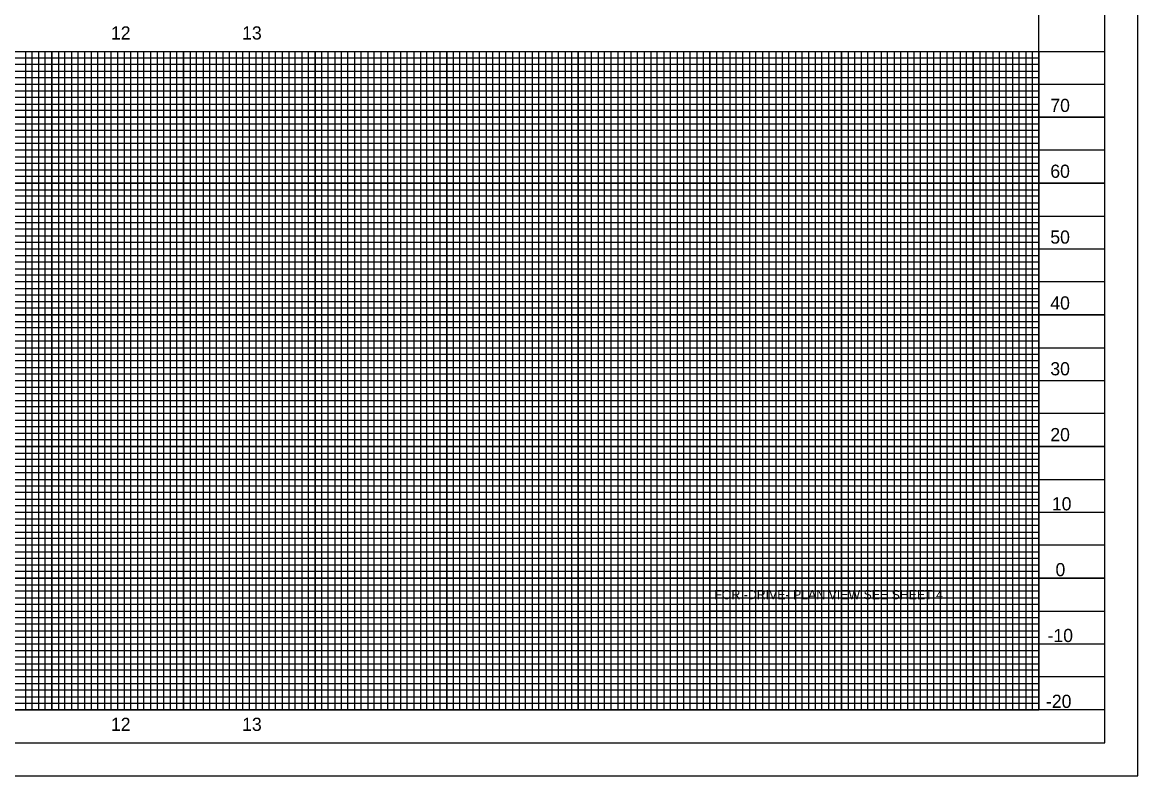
# Model space of a CAD drawing. Extents: x 1637092 to 1638792, y 884647 to 885778.
# Drawn here: x 1637944 to 1638792, y 884647 to 885219 of the extents above; entities that cross this region are included whole.
import ezdxf

# ---------------------------------------------------------------- set-up
doc = ezdxf.new("R2010")
doc.units = 0
for name, color, linetype in [('Exist Vertical Profile Horizontal Axis Label Major', 7, 'Continuous'), ('Exist Vertical Profile Vertical Axis Label', 7, 'Continuous'), ('Prop VPI Label', 7, 'Continuous'), ('Scratch_Level_3', 7, 'Continuous'), ('Sheet Cutting Line CELL', 7, 'Continuous'), ('Sheet DOT Grid CELL', 7, 'Continuous'), ('Sheet Layout Profile Border Port 2', 7, 'Continuous'), ('Sheet Plan And Profile CELL', 7, 'Continuous'), ('Sheet Profile CELL', 7, 'Continuous'), ('Sheet Profile Grid Major CELL', 7, 'Continuous'), ('Sheet Profile Grid Middle CELL', 7, 'Continuous'), ('Sheet Profile Grid Minor CELL', 7, 'Continuous'), ('Stewart Plot Border Xerox6279 and LJ5000', 7, 'Continuous')]:
    doc.layers.add(name, color=color, linetype=linetype)

msp = doc.modelspace()

# ---------------------------------------------------------------- linework, layer by layer
at = {"layer": 'Prop VPI Label'}
msp.add_lwpolyline([(1638466.66, 884797.14), (1638681.66, 884797.14), (1638681.66, 884772.14), (1638466.66, 884772.14)], close=True, dxfattribs=at)
msp.add_lwpolyline([(1638466.66, 884797.14), (1638681.66, 884797.14), (1638681.66, 884772.14), (1638466.66, 884772.14)], close=True, dxfattribs=at)
at = {"layer": 'Scratch_Level_3'}
msp.add_lwpolyline([(1637316.66, 885722.14), (1637316.66, 884697.14), (1638716.66, 884697.14), (1638716.66, 885777.71)], close=True, dxfattribs=at)
at = {"layer": 'Sheet Cutting Line CELL'}
msp.add_line((1637099.66, 884647.14), (1638783.66, 884647.14), dxfattribs=at)
at = {"layer": 'Sheet DOT Grid CELL'}
for p, q in [((1637266.66, 885197.14), (1638766.54, 885197.14)), ((1637966.66, 885197.14), (1637966.66, 884697.14)), ((1638016.66, 885197.14), (1638016.66, 884697.14)), ((1638066.66, 885197.14), (1638066.66, 884697.14)), ((1638116.66, 885197.14), (1638116.66, 884697.14)), ((1638166.66, 885197.14), (1638166.66, 884697.14)), ((1638216.66, 885197.14), (1638216.66, 884697.14)), ((1638266.66, 885197.14), (1638266.66, 884697.14)), ((1638316.66, 885197.14), (1638316.66, 884697.14)), ((1638366.66, 885197.14), (1638366.66, 884697.14)), ((1638416.66, 885197.14), (1638416.66, 884697.14)), ((1638466.66, 885197.14), (1638466.66, 884697.14)), ((1638516.66, 885197.14), (1638516.66, 884697.14)), ((1638566.66, 885197.14), (1638566.66, 884697.14)), ((1638616.66, 885197.14), (1638616.66, 884697.14)), ((1638666.66, 885197.14), (1638666.66, 884697.14)), ((1638716.66, 885197.14), (1638716.66, 884697.14)), ((1637266.66, 885147.14), (1638766.54, 885147.14)), ((1637266.66, 885097.14), (1638766.54, 885097.14)), ((1637266.66, 885047.14), (1638766.54, 885047.14)), ((1637266.66, 884997.14), (1638766.54, 884997.14)), ((1637266.66, 884947.14), (1638766.54, 884947.14)), ((1637266.66, 884897.14), (1638766.54, 884897.14)), ((1637266.66, 884847.14), (1638766.54, 884847.14)), ((1637266.66, 884797.14), (1638766.54, 884797.14)), ((1637266.66, 884747.14), (1638766.54, 884747.14))]:
    msp.add_line(p, q, dxfattribs=at)
at = {"layer": 'Sheet Layout Profile Border Port 2'}
msp.add_lwpolyline([(1637316.66, 885197.14), (1638716.66, 885197.14), (1638716.66, 884697.14), (1637316.66, 884697.14)], close=True, dxfattribs=at)
at = {"layer": 'Sheet Plan And Profile CELL'}
msp.add_lwpolyline([(1638766.66, 885722.14), (1637266.66, 885722.14), (1637266.66, 884672.14), (1638766.66, 884672.14)], close=True, dxfattribs=at)
at = {"layer": 'Sheet Profile CELL'}
for p, q in [((1637266.66, 885197.14), (1638766.66, 885197.14)), ((1638766.66, 884697.14), (1637266.66, 884697.14)), ((1638766.66, 884697.14), (1637266.66, 884697.14)), ((1637266.66, 884672.14), (1638766.66, 884672.14))]:
    msp.add_line(p, q, dxfattribs=at)
msp.add_lwpolyline([(1638766.66, 885722.14), (1637266.66, 885722.14), (1637266.66, 884672.14), (1638766.66, 884672.14)], close=True, dxfattribs=at)
at = {"layer": 'Sheet Profile Grid Major CELL'}
for p, q in [((1638266.66, 885197.14), (1638316.66, 885197.14)), ((1638366.66, 885197.14), (1638416.66, 885197.14)), ((1638466.66, 885197.14), (1638516.66, 885197.14)), ((1638566.66, 885197.14), (1638616.66, 885197.14)), ((1638666.66, 885197.14), (1638716.66, 885197.14)), ((1638666.66, 884697.14), (1638666.66, 884697.14))]:
    msp.add_line(p, q, dxfattribs=at)
for points in [[(1637916.66, 884697.14), (1637966.66, 884697.14), (1637966.66, 885197.14), (1638016.66, 885197.14), (1638016.66, 884697.14), (1638066.66, 884697.14), (1638066.66, 885197.14), (1638116.66, 885197.14), (1638116.66, 884697.14), (1638166.66, 884697.14), (1638166.66, 885197.14), (1638216.66, 885197.14), (1638216.66, 884697.14), (1638266.66, 884697.14), (1638266.66, 885197.14), (1638316.66, 885197.14), (1638316.66, 884697.14), (1638366.66, 884697.14), (1638366.66, 885197.14), (1638416.66, 885197.14), (1638416.66, 884697.14), (1638466.66, 884697.14), (1638466.66, 885197.14), (1638516.66, 885197.14), (1638516.66, 884697.14), (1638566.66, 884697.14), (1638566.66, 885197.14), (1638616.66, 885197.14), (1638616.66, 884697.14), (1638666.66, 884697.14), (1638666.66, 884697.14), (1638666.66, 885197.14), (1638716.66, 885197.14), (1638716.66, 884697.14)], [(1638766.66, 885147.14), (1637266.66, 885147.14)], [(1638766.66, 885097.14), (1637266.66, 885097.14), (1637266.66, 885047.14), (1638766.66, 885047.14)], [(1638766.66, 884997.14), (1637266.66, 884997.14), (1637266.66, 884947.14), (1638766.66, 884947.14)], [(1638766.66, 884897.14), (1637266.66, 884897.14), (1637266.66, 884847.14), (1638766.66, 884847.14)], [(1638766.66, 884797.14), (1637266.66, 884797.14), (1637266.66, 884797.14), (1637266.66, 884747.14), (1638766.66, 884747.14)], [(1638766.66, 884697.14), (1637266.66, 884697.14)]]:
    msp.add_lwpolyline(points, dxfattribs=at)
at = {"layer": 'Sheet Profile Grid Middle CELL'}
for points in [[(1637941.66, 884697.14), (1637991.66, 884697.14), (1637991.66, 885197.14), (1638041.66, 885197.14), (1638041.66, 884697.14), (1638091.66, 884697.14), (1638091.66, 885197.14), (1638141.66, 885197.14), (1638141.66, 884697.14), (1638191.66, 884697.14), (1638191.66, 885197.14), (1638241.66, 885197.14), (1638241.66, 884697.14), (1638291.66, 884697.14), (1638291.66, 885197.14), (1638341.66, 885197.14), (1638341.66, 884697.14), (1638391.66, 884697.14), (1638391.66, 885197.14), (1638441.66, 885197.14), (1638441.66, 884697.14), (1638491.66, 884697.14), (1638491.66, 885197.14), (1638541.66, 885197.14), (1638541.66, 884697.14), (1638591.66, 884697.14), (1638591.66, 885197.14), (1638641.66, 885197.14), (1638641.66, 884697.14), (1638691.66, 884697.14), (1638691.66, 885197.14)], [(1637266.66, 885172.14), (1638766.66, 885172.14)], [(1638766.66, 885122.14), (1637266.66, 885122.14), (1637266.66, 885072.14), (1638766.66, 885072.14)], [(1638766.66, 885022.14), (1637266.66, 885022.14), (1637266.66, 884972.14), (1638766.66, 884972.14)], [(1638766.66, 884922.14), (1637266.66, 884922.14), (1637266.66, 884872.14), (1638766.66, 884872.14)], [(1638766.66, 884822.14), (1637266.66, 884822.14), (1637266.66, 884772.14), (1638766.66, 884772.14)], [(1638766.66, 884722.14), (1637266.66, 884722.14)]]:
    msp.add_lwpolyline(points, dxfattribs=at)
at = {"layer": 'Sheet Profile Grid Minor CELL'}
for p, q in [((1637316.66, 885192.14), (1638716.66, 885192.14)), ((1638716.66, 885187.14), (1637316.66, 885187.14)), ((1637316.66, 885182.14), (1638716.66, 885182.14)), ((1638716.66, 885177.14), (1637316.66, 885177.14)), ((1637316.66, 885167.14), (1638716.66, 885167.14)), ((1638716.66, 885162.14), (1637316.66, 885162.14)), ((1637316.66, 885157.14), (1638716.66, 885157.14)), ((1638716.66, 885152.14), (1637316.66, 885152.14)), ((1637316.66, 885142.14), (1638716.66, 885142.14)), ((1638716.66, 885137.14), (1637316.66, 885137.14)), ((1637316.66, 885132.14), (1638716.66, 885132.14)), ((1638716.66, 885127.14), (1637316.66, 885127.14)), ((1637316.66, 885117.14), (1638716.66, 885117.14)), ((1638716.66, 885112.14), (1637316.66, 885112.14)), ((1637316.66, 885107.14), (1638716.66, 885107.14)), ((1638716.66, 885102.14), (1637316.66, 885102.14)), ((1637316.66, 885092.14), (1638716.66, 885092.14)), ((1638716.66, 885087.14), (1637316.66, 885087.14)), ((1637316.66, 885082.14), (1638716.66, 885082.14)), ((1638716.66, 885077.14), (1637316.66, 885077.14)), ((1637316.66, 885067.14), (1638716.66, 885067.14)), ((1638716.66, 885062.14), (1637316.66, 885062.14)), ((1637316.66, 885057.14), (1638716.66, 885057.14)), ((1638716.66, 885052.14), (1637316.66, 885052.14)), ((1637316.66, 885042.14), (1638716.66, 885042.14)), ((1638716.66, 885037.14), (1637316.66, 885037.14)), ((1637316.66, 885032.14), (1638716.66, 885032.14)), ((1638716.66, 885027.14), (1637316.66, 885027.14)), ((1637316.66, 885017.14), (1638716.66, 885017.14)), ((1638716.66, 885012.14), (1637316.66, 885012.14)), ((1637316.66, 885007.14), (1638716.66, 885007.14)), ((1638716.66, 885002.14), (1637316.66, 885002.29)), ((1637316.66, 884992.14), (1638716.66, 884992.14)), ((1638716.66, 884987.14), (1637316.66, 884987.14)), ((1637316.66, 884982.14), (1638716.66, 884982.14)), ((1638716.66, 884977.14), (1637316.66, 884977.14)), ((1637316.66, 884967.14), (1638716.66, 884967.14)), ((1638716.66, 884962.14), (1637316.66, 884962.14)), ((1637316.66, 884957.14), (1638716.66, 884957.14)), ((1638716.66, 884952.14), (1637316.66, 884952.14)), ((1637316.66, 884942.14), (1638716.66, 884942.14)), ((1638716.66, 884937.14), (1637316.66, 884937.14)), ((1637316.66, 884932.14), (1638716.66, 884932.14)), ((1638716.66, 884927.14), (1637316.66, 884927.14)), ((1637316.66, 884917.14), (1638716.66, 884917.14)), ((1638716.66, 884912.14), (1637316.66, 884912.14)), ((1637316.66, 884907.14), (1638716.66, 884907.14)), ((1638716.66, 884902.14), (1637316.66, 884902.14)), ((1637316.66, 884892.14), (1638716.66, 884892.14)), ((1638716.66, 884887.14), (1637316.66, 884887.14)), ((1637316.66, 884882.14), (1638716.66, 884882.14)), ((1638716.66, 884877.14), (1637316.66, 884877.14)), ((1637316.66, 884867.14), (1638716.66, 884867.14)), ((1638716.66, 884862.14), (1637316.66, 884862.14)), ((1637316.66, 884857.14), (1638716.66, 884857.14)), ((1638716.66, 884852.14), (1637316.66, 884852.14)), ((1637316.66, 884842.14), (1638716.66, 884842.14)), ((1638716.66, 884837.14), (1637316.66, 884837.14)), ((1637316.66, 884832.14), (1638716.66, 884832.14)), ((1638716.66, 884827.14), (1637316.66, 884827.14)), ((1637316.66, 884817.14), (1638716.66, 884817.14)), ((1638716.66, 884812.14), (1637316.66, 884812.14)), ((1637316.66, 884807.14), (1638716.66, 884807.14)), ((1638716.66, 884802.14), (1637316.66, 884802.14)), ((1637316.66, 884792.14), (1638716.66, 884792.14)), ((1638716.66, 884787.14), (1637316.66, 884787.14)), ((1637316.66, 884782.14), (1638716.66, 884782.14)), ((1638716.66, 884777.14), (1637316.66, 884777.14)), ((1637316.66, 884767.14), (1638716.66, 884767.14)), ((1638716.66, 884762.14), (1637316.66, 884762.14)), ((1637316.66, 884757.14), (1638716.66, 884757.14)), ((1638716.66, 884752.14), (1637316.66, 884752.14)), ((1637316.66, 884742.14), (1638716.66, 884742.14)), ((1638716.66, 884737.14), (1637316.66, 884737.14)), ((1637316.66, 884732.14), (1638716.66, 884732.14)), ((1638716.66, 884727.14), (1637316.66, 884727.14)), ((1637316.66, 884717.14), (1638716.66, 884717.14)), ((1638716.66, 884712.14), (1637316.66, 884712.14)), ((1637316.66, 884707.14), (1638716.66, 884707.14)), ((1637316.66, 884702.14), (1638716.66, 884702.14)), ((1638716.66, 884702.14), (1638716.66, 884702.14))]:
    msp.add_line(p, q, dxfattribs=at)
for points in [[(1637936.66, 885197.14), (1637946.66, 885197.14), (1637946.66, 884697.14), (1637951.66, 884697.14), (1637951.66, 885197.14), (1637956.66, 885197.14), (1637956.66, 884697.14), (1637961.66, 884697.14), (1637961.66, 885197.14), (1637971.66, 885197.14), (1637971.66, 884697.14), (1637971.66, 884697.14), (1637976.66, 884697.14), (1637976.66, 885197.14), (1637981.66, 885197.14), (1637981.66, 884697.14), (1637986.66, 884697.14), (1637986.66, 885197.14), (1637996.66, 885197.14), (1637996.66, 884697.14), (1638001.66, 884697.14), (1638001.66, 885197.14), (1638006.66, 885197.14), (1638006.66, 884697.14), (1638011.66, 884697.14), (1638011.66, 885197.14), (1638021.66, 885197.14), (1638021.66, 884697.14), (1638026.66, 884697.14), (1638026.66, 885197.14), (1638031.66, 885197.14), (1638031.66, 884697.14), (1638036.66, 884697.14), (1638036.66, 885197.14), (1638046.66, 885197.14), (1638046.66, 884697.14), (1638051.66, 884697.14), (1638051.66, 885197.14), (1638056.66, 885197.14), (1638056.66, 884697.14), (1638061.66, 884697.14), (1638061.66, 885197.14), (1638071.66, 885197.14), (1638071.66, 884697.14), (1638076.66, 884697.14), (1638076.66, 885197.14), (1638081.66, 885197.14), (1638081.66, 884697.14), (1638086.66, 884697.14), (1638086.66, 885197.14), (1638096.66, 885197.14), (1638096.66, 884697.14), (1638101.66, 884697.14), (1638101.66, 885197.14), (1638106.66, 885197.14), (1638106.66, 884697.14), (1638111.66, 884697.14), (1638111.66, 885197.14), (1638121.66, 885197.14), (1638121.66, 884697.14), (1638126.36, 884697.69), (1638126.66, 884697.14), (1638126.66, 885197.14), (1638131.66, 885197.14), (1638131.66, 884697.14), (1638136.66, 884697.14), (1638136.66, 885197.14), (1638146.66, 885197.14), (1638146.66, 884697.14), (1638151.66, 884697.14)], [(1638151.66, 884697.14), (1638151.66, 885197.14), (1638156.66, 885197.14), (1638156.66, 884697.14), (1638161.66, 884697.14), (1638161.66, 885197.14), (1638171.66, 885197.14), (1638171.66, 884697.14), (1638176.66, 884697.14), (1638176.66, 885197.14), (1638181.66, 885197.14), (1638181.66, 884697.14), (1638186.66, 884697.14), (1638186.66, 885197.14), (1638196.66, 885197.14), (1638196.66, 884697.14), (1638201.66, 884697.14), (1638201.66, 885197.14), (1638206.66, 885197.14), (1638206.66, 884697.14), (1638211.66, 884697.14), (1638211.66, 885197.14), (1638221.66, 885197.14), (1638221.66, 884697.14), (1638226.66, 884697.14), (1638226.66, 885197.14), (1638231.66, 885197.14), (1638231.66, 884697.14), (1638236.66, 884697.14), (1638236.66, 885197.14), (1638246.66, 885197.14), (1638246.66, 884697.14), (1638251.66, 884697.14), (1638251.66, 885197.14), (1638256.66, 885197.14), (1638256.66, 884697.14), (1638261.66, 884697.14), (1638261.66, 885197.14), (1638271.66, 885197.14), (1638271.66, 884697.14), (1638276.66, 884697.14), (1638276.66, 885197.14), (1638281.66, 885197.14), (1638281.66, 884697.14), (1638286.66, 884697.14), (1638286.66, 885197.14), (1638296.66, 885197.14), (1638296.66, 884697.14), (1638301.66, 884697.14), (1638301.66, 885197.14), (1638306.66, 885197.14), (1638306.66, 884697.14), (1638311.66, 884697.14), (1638311.66, 885197.14), (1638321.66, 885197.14), (1638321.66, 884697.14), (1638326.66, 884697.14), (1638326.66, 885197.14), (1638331.66, 885197.14), (1638331.66, 884697.14), (1638336.66, 884697.14), (1638336.66, 885197.14), (1638346.66, 885197.14), (1638346.66, 884697.14), (1638351.66, 884697.14), (1638351.66, 885197.14), (1638356.66, 885197.14), (1638356.66, 884697.14), (1638361.66, 884697.14), (1638361.66, 885197.14), (1638371.66, 885197.14), (1638371.66, 884697.14), (1638376.66, 884697.14), (1638376.66, 885197.14), (1638381.66, 885197.14), (1638381.66, 884697.14), (1638386.66, 884697.14), (1638386.66, 885197.14), (1638396.66, 885197.14), (1638396.66, 884697.14), (1638401.66, 884697.14), (1638401.66, 885197.14), (1638406.66, 885197.14), (1638406.66, 884697.14), (1638411.66, 884697.14), (1638411.66, 885197.14), (1638421.66, 885197.14), (1638421.66, 884697.14), (1638426.66, 884697.14), (1638426.66, 885197.14), (1638431.66, 885197.14), (1638431.66, 884697.14), (1638436.66, 884697.14), (1638436.66, 885197.14), (1638446.66, 885197.14), (1638446.66, 884697.14), (1638451.66, 884697.14), (1638451.66, 885197.14), (1638456.66, 885197.14), (1638456.66, 884697.14)], [(1638456.66, 884697.14), (1638461.66, 884697.14), (1638461.66, 885197.14), (1638471.66, 885197.14), (1638471.66, 884697.14), (1638476.66, 884697.14), (1638476.66, 885197.14), (1638481.66, 885197.14), (1638481.66, 884697.14), (1638486.66, 884697.14), (1638486.66, 885197.14), (1638496.66, 885197.14), (1638496.66, 884697.14), (1638501.66, 884697.14), (1638501.66, 885197.14), (1638506.66, 885197.14), (1638506.66, 884697.14), (1638511.66, 884697.14), (1638511.66, 885197.14), (1638521.66, 885197.14), (1638521.66, 884697.14), (1638526.66, 884697.14), (1638526.66, 885197.14), (1638531.66, 885197.14), (1638531.66, 884697.14), (1638536.66, 884697.14), (1638536.66, 885197.14), (1638546.66, 885197.14), (1638546.66, 884697.14), (1638551.66, 884697.14), (1638551.66, 885197.14), (1638556.66, 885197.14), (1638556.66, 884697.14), (1638561.66, 884697.14), (1638561.66, 885197.14), (1638571.66, 885197.14), (1638571.66, 884697.14), (1638576.66, 884697.14), (1638576.66, 885197.14), (1638581.66, 885197.14), (1638581.66, 884697.14), (1638586.66, 884697.14), (1638586.66, 885197.14), (1638596.66, 885197.14), (1638596.66, 884697.14), (1638601.66, 884697.14), (1638601.66, 885197.14), (1638606.66, 885197.14), (1638606.66, 884697.14), (1638611.66, 884697.14), (1638611.66, 885197.14), (1638621.66, 885197.14), (1638621.66, 884697.14), (1638626.66, 884697.14), (1638626.66, 885197.14), (1638631.66, 885197.14), (1638631.66, 884697.14), (1638636.66, 884697.14), (1638636.66, 885197.14), (1638646.66, 885197.14), (1638646.66, 884697.14), (1638651.66, 884697.14), (1638651.66, 885197.14), (1638656.66, 885197.14), (1638656.66, 884697.14), (1638661.66, 884697.14), (1638661.66, 885197.14), (1638671.66, 885197.14), (1638671.66, 884697.14), (1638676.66, 884697.14), (1638676.66, 885197.14), (1638681.66, 885197.14), (1638681.66, 884697.14), (1638686.66, 884697.14), (1638686.66, 885197.14), (1638696.66, 885197.14), (1638696.66, 884697.14), (1638701.66, 884697.14), (1638701.66, 885197.14), (1638706.66, 885197.14), (1638706.66, 884697.14), (1638711.66, 884697.14), (1638711.66, 885197.14), (1638716.66, 885197.14)]]:
    msp.add_lwpolyline(points, dxfattribs=at)
at = {"layer": 'Stewart Plot Border Xerox6279 and LJ5000'}
msp.add_lwpolyline([(1637091.66, 884647.14), (1638791.66, 884647.14), (1638791.66, 885747.14), (1637091.66, 885747.14)], close=True, dxfattribs=at)

# ---------------------------------------------------------------- texts
at = {"layer": 'Exist Vertical Profile Horizontal Axis Label Major'}
for s, p in [('12', (1638011.59, 885206.16)), ('13', (1638111.26, 885206.16)), ('12', (1638011.59, 884681.16)), ('13', (1638111.26, 884681.16))]:
    msp.add_text(s, height=10, dxfattribs=at).set_placement(p)
at = {"layer": 'Exist Vertical Profile Vertical Axis Label'}
for s, p in [('70', (1638725.27, 885151.15)), ('60', (1638725.27, 885101.15)), ('50', (1638725.27, 885051.15)), ('40', (1638725.27, 885001.15)), ('30', (1638725.27, 884951.15)), ('20', (1638725.27, 884901.15)), ('10', (1638726.46, 884848.61)), ('0', (1638729.22, 884798.61)), ('-10', (1638723.19, 884748.61)), ('-20', (1638721.99, 884698.61))]:
    msp.add_text(s, height=10, dxfattribs=at).set_placement(p)
at = {"layer": 'Prop VPI Label'}
msp.add_text('FOR -DRIVE- PLAN VIEW SEE SHEET 4', height=7, dxfattribs=at).set_placement((1638469.99, 884781.14))

doc.saveas('drawing.dxf')
